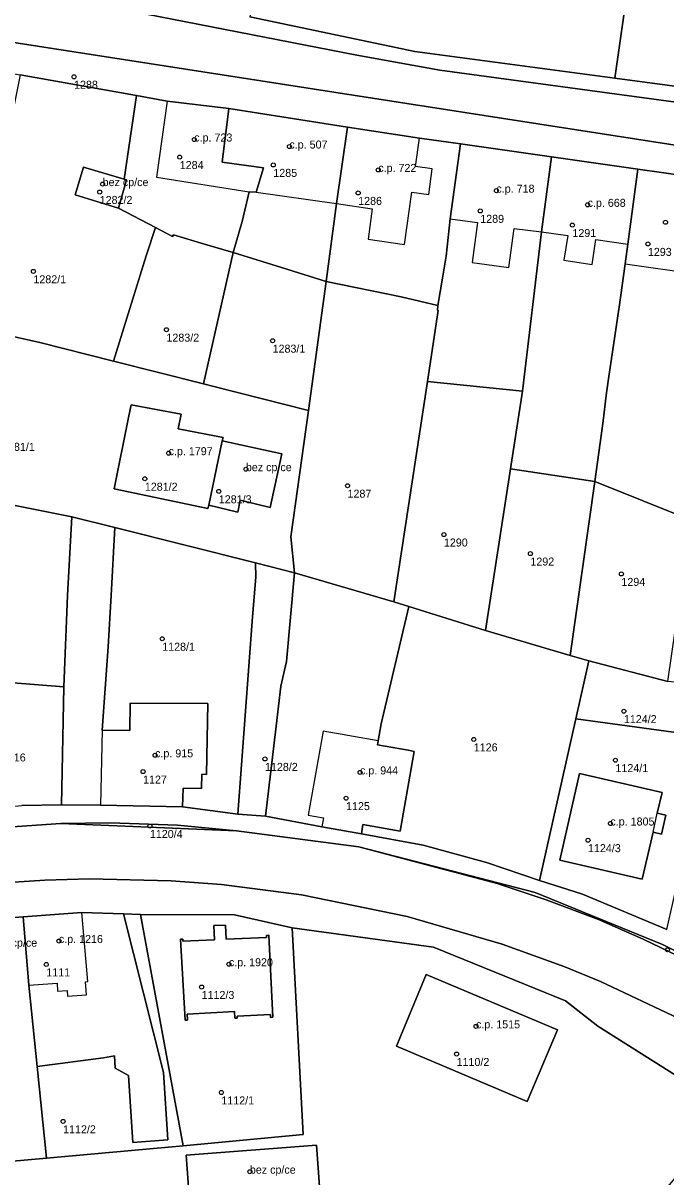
# Model space of a CAD drawing. Extents: x -878211 to -870363, y -1058464 to -1052522.
# Drawn here: x -875220.6 to -875140.3, y -1056399.9 to -1056255.7 of the extents above; entities that cross this region are included whole.
import ezdxf

# ---------------------------------------------------------------- set-up
doc = ezdxf.new("R2010")
doc.units = 0
for name, color, linetype in [('Definiční body', 7, 'Continuous'), ('Polygon budovy', 7, 'Continuous'), ('Polygon parcely', 7, 'Continuous')]:
    doc.layers.add(name, color=color, linetype=linetype)

msp = doc.modelspace()

# ---------------------------------------------------------------- linework, layer by layer
at = {"layer": 'Definiční body'}
for centre in [(-875214.21, -1056262.45994), (-875199.2, -1056270.28994), (-875187.31, -1056271.16994), (-875201.01, -1056272.48994), (-875189.32, -1056273.46994), (-875176.21, -1056274.08994), (-875211.01, -1056276.84994), (-875210.64, -1056275.85994), (-875178.72, -1056276.96994), (-875161.45, -1056276.67994), (-875150.06, -1056278.44994), (-875163.47, -1056279.20994), (-875151.96, -1056280.97994), (-875140.33, -1056280.62994), (-875142.53, -1056283.33994), (-875219.29, -1056286.75994), (-875202.67, -1056294.04994), (-875189.41, -1056295.42994), (-875202.4, -1056309.46994), (-875192.75, -1056311.46994), (-875205.37, -1056312.66994), (-875196.13, -1056314.23994), (-875180.05, -1056313.53994), (-875168.01, -1056319.63994), (-875157.21, -1056322.01994), (-875145.84, -1056324.55994), (-875203.2, -1056332.65994), (-875145.53, -1056341.69994), (-875164.28, -1056345.22994), (-875204.09, -1056347.20994), (-875190.36, -1056347.66994), (-875146.58, -1056347.81994), (-875205.59, -1056349.24994), (-875178.49, -1056349.34994), (-875180.23, -1056352.56994), (-875204.74, -1056356.04994), (-875147.21, -1056355.72994), (-875150.01, -1056357.81994), (-875216.11, -1056370.40994), (-875140.09, -1056371.49994), (-875217.68, -1056373.33994), (-875194.87, -1056373.30994), (-875198.28, -1056376.15994), (-875164, -1056381.06994), (-875166.43, -1056384.52994), (-875195.81, -1056389.32994), (-875215.58, -1056392.93994), (-875192.25, -1056399.21994)]:
    msp.add_circle(centre, 0.25, dxfattribs=at)
at = {"layer": 'Polygon budovy'}
for points in [[(-875202.57, -1056265.49), (-875203.92, -1056274.99), (-875192.33, -1056276.81), (-875191.47, -1056276.86), (-875190.56, -1056273.84), (-875195.72, -1056273.13), (-875194.86, -1056266.4)], [(-875195.72, -1056273.13), (-875190.56, -1056273.84), (-875191.47, -1056276.86), (-875181.41, -1056278.29), (-875180.06, -1056268.76), (-875194.86, -1056266.4)], [(-875181.41, -1056278.29), (-875176.96, -1056278.96), (-875177.48, -1056282.72), (-875172.95, -1056283.4), (-875172.02, -1056276.88), (-875169.91, -1056277.17), (-875169.48, -1056273.97), (-875171.56, -1056273.68), (-875171.07, -1056270.14), (-875180.06, -1056268.76)], [(-875165.93, -1056270.84), (-875167.22, -1056280.18), (-875163.8, -1056280.65), (-875164.49, -1056285.66), (-875159.9, -1056286.29), (-875159.23, -1056281.4), (-875155.83, -1056281.83), (-875154.56, -1056272.47)], [(-875155.83, -1056281.83), (-875152.55, -1056282.29), (-875153.05, -1056285.38), (-875149.49, -1056285.91), (-875149.02, -1056282.76), (-875145.04, -1056283.35), (-875143.8, -1056273.98), (-875154.56, -1056272.47)], [(-875214.07, -1056277.19), (-875208.66, -1056278.87), (-875207.68, -1056275.34), (-875207.97, -1056275.25), (-875213.03, -1056273.73)], [(-875145.04, -1056283.35), (-875145.36, -1056285.83), (-875136.58, -1056287.05), (-875134.93, -1056275.24), (-875143.8, -1056273.98)], [(-875200.84, -1056304.61), (-875207.07, -1056303.42), (-875207.4, -1056305.03), (-875209.2, -1056313.93), (-875197.48, -1056316.38), (-875197.39, -1056315.98), (-875195.69, -1056307.93), (-875195.6, -1056307.52), (-875201.2, -1056306.43)], [(-875193.75, -1056316.82), (-875193.45, -1056315.36), (-875189.72, -1056316.27), (-875188.26, -1056309.57), (-875195.69, -1056307.93), (-875197.39, -1056315.98)], [(-875207.2, -1056340.68), (-875207.25, -1056344.13), (-875210.71, -1056344.08), (-875210.92, -1056353.44), (-875200.68, -1056353.65), (-875200.6, -1056351.3), (-875198.28, -1056351.37), (-875198.23, -1056349.55), (-875197.68, -1056349.59), (-875197.51, -1056340.74)], [(-875184.97, -1056354.7), (-875183.06, -1056355.04), (-875183.26, -1056356.13), (-875178.32, -1056357), (-875178.13, -1056355.87), (-875173.49, -1056356.67), (-875171.71, -1056346.72), (-875172.46, -1056346.58), (-875176.3, -1056345.89), (-875176.21, -1056345.39), (-875183.08, -1056344.18)], [(-875151.09, -1056349.5), (-875153.52, -1056360.3), (-875143.24, -1056362.68), (-875141.89, -1056356.81), (-875141.35, -1056354.44), (-875140.76, -1056351.84)], [(-875212.79, -1056375.5), (-875212.51, -1056375.48), (-875213.23, -1056366.84), (-875220.56, -1056367.39), (-875219.86, -1056375.93), (-875216.34, -1056375.68), (-875216.27, -1056376.69), (-875215.09, -1056376.6), (-875215.04, -1056377.31), (-875212.66, -1056377.14)], [(-875200.08, -1056379.54), (-875194.18, -1056379.2), (-875194.13, -1056380.05), (-875193.83, -1056380.03), (-875193.84, -1056379.81), (-875189.69, -1056379.57), (-875189.67, -1056379.95), (-875189.37, -1056379.93), (-875189.86, -1056369.68), (-875190.16, -1056369.7), (-875190.16, -1056369.95), (-875195.22, -1056370.16), (-875195.29, -1056368.42), (-875196.77, -1056368.46), (-875196.68, -1056370.26), (-875200.63, -1056370.44), (-875200.64, -1056370.17), (-875200.93, -1056370.19), (-875200.34, -1056380.31), (-875200.04, -1056380.29)], [(-875173.95, -1056383.55), (-875157.61, -1056390.46), (-875153.81, -1056381.51), (-875170.22, -1056374.59)], [(-875183.93, -1056395.9), (-875200.2, -1056397.17), (-875199.65, -1056404.55), (-875183.4, -1056403.37)]]:
    msp.add_lwpolyline(points, close=True, dxfattribs=at)
at = {"layer": 'Polygon parcely'}
for points in [[(-875192.25, -1056254.98), (-875171.65, -1056259.31), (-875146.64, -1056262.62), (-875145.45, -1056254.19), (-875143.49, -1056240.36), (-875142.76, -1056235.27), (-875163.85, -1056231.52), (-875186.44, -1056227.59)], [(-875146.64, -1056262.62), (-875100.28, -1056268.85), (-875099.3, -1056262.14), (-875092.6, -1056263.05), (-875091.28, -1056254.4), (-875090.54, -1056254.77), (-875089.5, -1056246.85), (-875096.96, -1056245.76), (-875099.09, -1056260.33), (-875130.54, -1056255.84), (-875128.5, -1056241.21), (-875121.77, -1056242.17), (-875121.8, -1056242.36), (-875116.62, -1056243.08), (-875116.46, -1056241.92), (-875140.94, -1056235.59), (-875142.76, -1056235.27), (-875143.49, -1056240.36), (-875145.45, -1056254.19)], [(-875209.27, -1056297.99), (-875205.22, -1056284.84), (-875204.02, -1056281.27), (-875208.66, -1056278.87), (-875214.07, -1056277.19), (-875213.03, -1056273.73), (-875207.97, -1056275.25), (-875206.4, -1056264.8), (-875220.93, -1056262.2), (-875223.93, -1056277.04), (-875226.69, -1056276.6), (-875229.33, -1056293.22), (-875218.47, -1056295.66)], [(-875201.8, -1056282.21), (-875197.91, -1056283.35), (-875194.35, -1056284.4), (-875193.23, -1056280.52), (-875192.33, -1056276.81), (-875191.47, -1056276.86), (-875190.56, -1056273.84), (-875195.72, -1056273.13), (-875194.86, -1056266.4), (-875202.57, -1056265.49), (-875206.4, -1056264.8), (-875207.97, -1056275.25), (-875207.68, -1056275.34), (-875208.66, -1056278.87), (-875204.02, -1056281.27), (-875201.92, -1056282.42)], [(-875188.3, -1056286.27), (-875182.73, -1056288.01), (-875181.41, -1056278.29), (-875180.06, -1056268.76), (-875194.86, -1056266.4), (-875195.72, -1056273.13), (-875190.56, -1056273.84), (-875191.47, -1056276.86), (-875192.33, -1056276.81), (-875193.23, -1056280.52), (-875194.35, -1056284.4)], [(-875182.73, -1056288.01), (-875173.36, -1056289.95), (-875168.76, -1056291.01), (-875168.18, -1056287.6), (-875167.71, -1056284.87), (-875167.22, -1056280.18), (-875165.93, -1056270.84), (-875171.07, -1056270.14), (-875180.06, -1056268.76), (-875181.41, -1056278.29)], [(-875167.22, -1056280.18), (-875167.71, -1056284.87), (-875168.18, -1056287.6), (-875168.76, -1056291.01), (-875168.83, -1056291.61), (-875168.72, -1056291.64), (-875170.07, -1056300.5), (-875158.18, -1056301.72), (-875155.83, -1056281.83), (-875154.56, -1056272.47), (-875165.93, -1056270.84)], [(-875149.17, -1056313.02), (-875148.15, -1056305.75), (-875147.69, -1056301.93), (-875147.43, -1056300.19), (-875146.14, -1056291.49), (-875146.1, -1056291.25), (-875145.36, -1056285.83), (-875145.04, -1056283.35), (-875143.8, -1056273.98), (-875154.56, -1056272.47), (-875155.83, -1056281.83), (-875158.18, -1056301.72), (-875159.68, -1056311.41)], [(-875208.66, -1056278.87), (-875207.68, -1056275.34), (-875207.97, -1056275.25), (-875213.03, -1056273.73), (-875214.07, -1056277.19)], [(-875137.13, -1056317.85), (-875134.54, -1056299.86), (-875134.06, -1056296.75), (-875133.71, -1056293.63), (-875133.17, -1056289.86), (-875131.07, -1056275.73), (-875134.93, -1056275.24), (-875143.8, -1056273.98), (-875145.04, -1056283.35), (-875145.36, -1056285.83), (-875146.1, -1056291.25), (-875146.14, -1056291.49), (-875147.43, -1056300.19), (-875147.69, -1056301.93), (-875148.15, -1056305.75), (-875149.17, -1056313.02)], [(-875194.35, -1056284.4), (-875197.91, -1056283.35), (-875201.8, -1056282.21), (-875201.92, -1056282.42), (-875204.02, -1056281.27), (-875205.22, -1056284.84), (-875209.27, -1056297.99), (-875198.04, -1056300.81)], [(-875198.04, -1056300.81), (-875196.77, -1056301.13), (-875184.93, -1056304.16), (-875182.73, -1056288.01), (-875188.3, -1056286.27), (-875194.35, -1056284.4)], [(-875182.73, -1056288.01), (-875184.93, -1056304.16), (-875187.15, -1056319.92), (-875186.69, -1056324.41), (-875174.26, -1056328.03), (-875170.07, -1056300.5), (-875168.72, -1056291.64), (-875168.83, -1056291.61), (-875168.76, -1056291.01), (-875173.36, -1056289.95)], [(-875184.93, -1056304.16), (-875196.77, -1056301.13), (-875198.04, -1056300.81), (-875209.27, -1056297.99), (-875218.47, -1056295.66), (-875229.33, -1056293.22), (-875229.96, -1056296.23), (-875232.61, -1056313.8), (-875214.5, -1056317.42), (-875209.11, -1056318.77), (-875191.55, -1056323.16), (-875186.69, -1056324.41), (-875187.15, -1056319.92)], [(-875158.18, -1056301.72), (-875170.07, -1056300.5), (-875174.26, -1056328.03), (-875172.4, -1056328.62), (-875162.8, -1056331.64), (-875159.68, -1056311.41)], [(-875195.69, -1056307.93), (-875195.6, -1056307.52), (-875201.2, -1056306.43), (-875200.84, -1056304.61), (-875207.07, -1056303.42), (-875207.4, -1056305.03), (-875209.2, -1056313.93), (-875197.48, -1056316.38), (-875197.39, -1056315.98)], [(-875195.69, -1056307.93), (-875188.26, -1056309.57), (-875189.72, -1056316.27), (-875193.45, -1056315.36), (-875193.75, -1056316.82), (-875197.39, -1056315.98), (-875197.48, -1056316.38), (-875209.2, -1056313.93), (-875207.4, -1056305.03), (-875207.07, -1056303.42), (-875200.84, -1056304.61), (-875201.2, -1056306.43), (-875195.6, -1056307.52)], [(-875197.39, -1056315.98), (-875193.75, -1056316.82), (-875193.45, -1056315.36), (-875189.72, -1056316.27), (-875188.26, -1056309.57), (-875195.69, -1056307.93)], [(-875149.17, -1056313.02), (-875159.68, -1056311.41), (-875162.8, -1056331.64), (-875152.23, -1056334.75)], [(-875215.01, -1056327.24), (-875214.5, -1056317.42), (-875232.61, -1056313.8), (-875231.57, -1056331.78), (-875226.06, -1056332.37), (-875226.49, -1056336.38), (-875226.66, -1056337.79), (-875215.5, -1056338.65)], [(-875137.13, -1056317.85), (-875149.17, -1056313.02), (-875152.23, -1056334.75), (-875149.92, -1056335.39), (-875140.03, -1056338)], [(-875215.5, -1056338.65), (-875215.78, -1056353.41), (-875210.92, -1056353.44), (-875200.68, -1056353.65), (-875200.6, -1056351.3), (-875198.28, -1056351.37), (-875198.23, -1056349.55), (-875197.68, -1056349.59), (-875197.51, -1056340.74), (-875207.2, -1056340.68), (-875207.25, -1056344.13), (-875210.71, -1056344.08), (-875209.97, -1056333.68), (-875209.59, -1056327.26), (-875209.11, -1056318.77), (-875214.5, -1056317.42), (-875215.01, -1056327.24)], [(-875191.55, -1056323.16), (-875209.11, -1056318.77), (-875209.59, -1056327.26), (-875209.97, -1056333.68), (-875210.71, -1056344.08), (-875207.25, -1056344.13), (-875207.2, -1056340.68), (-875197.51, -1056340.74), (-875197.68, -1056349.59), (-875198.23, -1056349.55), (-875198.28, -1056351.37), (-875200.6, -1056351.3), (-875200.68, -1056353.65), (-875193.76, -1056354.57), (-875191.9, -1056329.92), (-875191.52, -1056324.94)], [(-875191.55, -1056323.16), (-875191.52, -1056324.94), (-875191.9, -1056329.92), (-875193.76, -1056354.57), (-875190.28, -1056354.81), (-875188.95, -1056343.56), (-875188.37, -1056338.56), (-875187.68, -1056335.49), (-875186.69, -1056324.41)], [(-875183.26, -1056356.13), (-875178.32, -1056357), (-875178.13, -1056355.87), (-875173.49, -1056356.67), (-875171.71, -1056346.72), (-875172.46, -1056346.58), (-875176.3, -1056345.89), (-875176.21, -1056345.39), (-875175.84, -1056343.29), (-875172.4, -1056328.62), (-875174.26, -1056328.03), (-875186.69, -1056324.41), (-875187.68, -1056335.49), (-875188.37, -1056338.56), (-875188.95, -1056343.56), (-875190.28, -1056354.81)], [(-875170.6, -1056358.44), (-875162.71, -1056360.61), (-875156.07, -1056362.83), (-875151.54, -1056342.64), (-875149.92, -1056335.39), (-875152.23, -1056334.75), (-875162.8, -1056331.64), (-875172.4, -1056328.62), (-875175.84, -1056343.29), (-875176.21, -1056345.39), (-875176.3, -1056345.89), (-875172.46, -1056346.58), (-875171.71, -1056346.72), (-875173.49, -1056356.67), (-875178.13, -1056355.87), (-875178.32, -1056357)], [(-875220.75, -1056353.48), (-875215.78, -1056353.41), (-875215.5, -1056338.65), (-875226.66, -1056337.79), (-875226.49, -1056336.38), (-875226.06, -1056332.37), (-875231.57, -1056331.78), (-875231.16, -1056335.82), (-875230.75, -1056340.36), (-875230.31, -1056345.3), (-875229.41, -1056354.3)], [(-875151.54, -1056342.64), (-875134.75, -1056344.94), (-875133.33, -1056338.6), (-875140.03, -1056338), (-875149.92, -1056335.39)], [(-875150.71, -1056364.56), (-875140.15, -1056368.99), (-875137, -1056354.96), (-875134.75, -1056344.94), (-875151.54, -1056342.64), (-875156.07, -1056362.83)], [(-875153.52, -1056360.3), (-875143.24, -1056362.68), (-875141.89, -1056356.81), (-875140.81, -1056357.05), (-875140.28, -1056354.68), (-875141.35, -1056354.44), (-875140.76, -1056351.84), (-875151.09, -1056349.5)], [(-875153.52, -1056360.3), (-875151.09, -1056349.5), (-875140.76, -1056351.84), (-875141.35, -1056354.44), (-875140.28, -1056354.68), (-875140.81, -1056357.05), (-875141.89, -1056356.81), (-875143.24, -1056362.68)], [(-875215.85, -1056355.72), (-875193.92, -1056356.66), (-875201.3, -1056355.92), (-875209.72, -1056355.65)], [(-875140.69, -1056370.83), (-875156.63, -1056364.33), (-875178.63, -1056358.65), (-875161.34, -1056363.22), (-875155.23, -1056365.27), (-875148.68, -1056367.74), (-875143.11, -1056370.16), (-875126.03, -1056378.37), (-875124.79, -1056378.79)], [(-875218.82, -1056386.07), (-875219.86, -1056375.93), (-875220.56, -1056367.39), (-875223.22, -1056367.59), (-875222.58, -1056373.85), (-875226.22, -1056374.28), (-875226.86, -1056367.97), (-875230.49, -1056368.33), (-875230.06, -1056372.07), (-875228.79, -1056383.11), (-875227.04, -1056398.38), (-875217.64, -1056397.55)], [(-875218.82, -1056386.07), (-875210.54, -1056385), (-875209.14, -1056384.75), (-875209.07, -1056386.31), (-875207.43, -1056387.19), (-875206.85, -1056395.59), (-875202.5, -1056395.26), (-875203.04, -1056386.84), (-875208.05, -1056367.03), (-875213.23, -1056366.84), (-875220.56, -1056367.39), (-875219.86, -1056375.93)], [(-875217.64, -1056397.55), (-875200.57, -1056396.01), (-875205.91, -1056367.11), (-875208.05, -1056367.03), (-875203.04, -1056386.84), (-875202.5, -1056395.26), (-875206.85, -1056395.59), (-875207.43, -1056387.19), (-875209.07, -1056386.31), (-875209.14, -1056384.75), (-875210.54, -1056385), (-875218.82, -1056386.07)], [(-875200.57, -1056396.01), (-875185.58, -1056394.58), (-875186.95, -1056368.75), (-875194.18, -1056367.12), (-875205.91, -1056367.11)], [(-875200.57, -1056396.01), (-875217.64, -1056397.55), (-875227.04, -1056398.38), (-875237.58, -1056399.31), (-875235.99, -1056416.34), (-875254.11, -1056418.23), (-875254.73, -1056418.15), (-875247.86, -1056467.52), (-875278.14, -1056485.01), (-875275.46, -1056496.62), (-875270.88, -1056517.13), (-875266.18, -1056516.99), (-875187.17, -1056501.5), (-875197.07, -1056487.59), (-875170.85, -1056444.56), (-875168.16, -1056440.42), (-875162.37, -1056427.89), (-875132.07, -1056391.57), (-875148.79, -1056381.04), (-875152.82, -1056377.86), (-875169.32, -1056371.19), (-875186.95, -1056368.75), (-875185.58, -1056394.58)], [(-875196.68, -1056370.26), (-875200.63, -1056370.44), (-875200.64, -1056370.17), (-875200.93, -1056370.19), (-875200.34, -1056380.31), (-875200.04, -1056380.29), (-875200.08, -1056379.54), (-875194.18, -1056379.2), (-875194.13, -1056380.05), (-875193.83, -1056380.03), (-875193.84, -1056379.81), (-875189.69, -1056379.57), (-875189.67, -1056379.95), (-875189.37, -1056379.93), (-875189.86, -1056369.68), (-875190.16, -1056369.7), (-875190.16, -1056369.95), (-875195.22, -1056370.16), (-875195.29, -1056368.42), (-875196.77, -1056368.46)], [(-875196.68, -1056370.26), (-875196.77, -1056368.46), (-875195.29, -1056368.42), (-875195.22, -1056370.16), (-875190.16, -1056369.95), (-875190.16, -1056369.7), (-875189.86, -1056369.68), (-875189.37, -1056379.93), (-875189.67, -1056379.95), (-875189.69, -1056379.57), (-875193.84, -1056379.81), (-875193.83, -1056380.03), (-875194.13, -1056380.05), (-875194.18, -1056379.2), (-875200.08, -1056379.54), (-875200.04, -1056380.29), (-875200.34, -1056380.31), (-875200.93, -1056370.19), (-875200.64, -1056370.17), (-875200.63, -1056370.44)], [(-875157.61, -1056390.46), (-875153.81, -1056381.51), (-875170.22, -1056374.59), (-875173.95, -1056383.55)], [(-875157.61, -1056390.46), (-875173.95, -1056383.55), (-875170.22, -1056374.59), (-875153.81, -1056381.51)], [(-875183.93, -1056395.9), (-875200.2, -1056397.17), (-875199.65, -1056404.55), (-875183.4, -1056403.37)], [(-875183.93, -1056395.9), (-875183.4, -1056403.37), (-875199.65, -1056404.55), (-875200.2, -1056397.17)]]:
    msp.add_lwpolyline(points, close=True, dxfattribs=at)
for points in [[(-875134.42, -1056266.24), (-875168.5, -1056261.62), (-875178.88, -1056259.75), (-875211.79, -1056253.35), (-875239.65, -1056248.32), (-875262.18, -1056244.25), (-875281.49, -1056241.14), (-875288.38, -1056240.11), (-875292.78, -1056239.47), (-875294.43, -1056238.67)], [(-875076.87, -1056280.65), (-875298.24, -1056246.26), (-875300.2, -1056248.02), (-875292.88, -1056249.17), (-875281.01, -1056251.4), (-875271.78, -1056253.11), (-875268.54, -1056253.62), (-875262.65, -1056254.71), (-875256.18, -1056255.88), (-875249.73, -1056257.07), (-875244.49, -1056257.99), (-875242.9, -1056258.33), (-875234.19, -1056259.84), (-875225.15, -1056261.48), (-875220.93, -1056262.2), (-875206.4, -1056264.8), (-875202.57, -1056265.49), (-875194.86, -1056266.4), (-875180.06, -1056268.76), (-875171.07, -1056270.14), (-875165.93, -1056270.84), (-875154.56, -1056272.47), (-875143.8, -1056273.98), (-875134.93, -1056275.24)], [(-875300.2, -1056248.02), (-875298.24, -1056246.26), (-875076.87, -1056280.65)], [(-875211.79, -1056253.35), (-875178.88, -1056259.75), (-875168.5, -1056261.62), (-875134.42, -1056266.24)], [(-875100.28, -1056268.85), (-875146.64, -1056262.62), (-875171.65, -1056259.31), (-875192.25, -1056254.98)], [(-875140.15, -1056368.99), (-875150.71, -1056364.56), (-875156.07, -1056362.83), (-875162.71, -1056360.61), (-875170.6, -1056358.44), (-875178.32, -1056357), (-875183.26, -1056356.13), (-875190.28, -1056354.81), (-875193.76, -1056354.57), (-875200.68, -1056353.65), (-875210.92, -1056353.44), (-875215.78, -1056353.41), (-875220.75, -1056353.48)], [(-875409.01, -1056395.8), (-875400.76, -1056392.35), (-875383.29, -1056385.23), (-875375.34, -1056382.19), (-875367.42, -1056379.44), (-875352.88, -1056375.12), (-875344.63, -1056373.02), (-875337.67, -1056371.42), (-875325.65, -1056368.89), (-875301.06, -1056364.21), (-875283.21, -1056361.69), (-875277.03, -1056360.91), (-875267.21, -1056359.9), (-875241.87, -1056357.54), (-875215.85, -1056355.72), (-875209.72, -1056355.65), (-875201.3, -1056355.92), (-875193.92, -1056356.66), (-875178.63, -1056358.65), (-875156.63, -1056364.33), (-875140.69, -1056370.83), (-875124.79, -1056378.79)], [(-875178.63, -1056358.65), (-875193.92, -1056356.66), (-875215.85, -1056355.72), (-875241.87, -1056357.54), (-875301.06, -1056364.21), (-875325.65, -1056368.89), (-875333.52, -1056370.91), (-875336.44, -1056371.66), (-875357.27, -1056377.02), (-875390.07, -1056388.31), (-875408.68, -1056396.75)], [(-875126.03, -1056378.37), (-875143.11, -1056370.16), (-875148.68, -1056367.74), (-875155.23, -1056365.27), (-875161.34, -1056363.22), (-875178.63, -1056358.65)], [(-875306.02, -1056372.36), (-875292.24, -1056370.08), (-875280.78, -1056368.45), (-875259.86, -1056366.33), (-875232.06, -1056363.91), (-875224.33, -1056363.24), (-875217.87, -1056362.82), (-875212.3, -1056362.66), (-875202.09, -1056362.9), (-875195.78, -1056363.36), (-875185.82, -1056364.63), (-875172.58, -1056367.36), (-875160.72, -1056370.8), (-875152.9, -1056373.65), (-875148.44, -1056375.46), (-875129.04, -1056384.62)], [(-875129.04, -1056384.62), (-875148.44, -1056375.46), (-875152.9, -1056373.65), (-875160.72, -1056370.8), (-875172.58, -1056367.36), (-875185.82, -1056364.63), (-875195.78, -1056363.36), (-875202.09, -1056362.9), (-875212.3, -1056362.66), (-875217.87, -1056362.82), (-875224.33, -1056363.24), (-875232.06, -1056363.91), (-875259.86, -1056366.33), (-875280.78, -1056368.45), (-875292.24, -1056370.08), (-875306.02, -1056372.36)], [(-875326.1, -1056378.2), (-875297.94, -1056375.24), (-875274.52, -1056372.72), (-875272.16, -1056373.18), (-875259.77, -1056372.06), (-875254.93, -1056371.72), (-875249.82, -1056371.56), (-875249.94, -1056370.25), (-875240.65, -1056369.3), (-875232.98, -1056368.57), (-875230.49, -1056368.33), (-875226.86, -1056367.97), (-875223.22, -1056367.59), (-875220.56, -1056367.39), (-875213.23, -1056366.84), (-875208.05, -1056367.03), (-875205.91, -1056367.11), (-875194.18, -1056367.12), (-875186.95, -1056368.75), (-875169.32, -1056371.19), (-875152.82, -1056377.86), (-875148.79, -1056381.04), (-875132.07, -1056391.57)]]:
    msp.add_lwpolyline(points, dxfattribs=at)

# ---------------------------------------------------------------- texts
at = {"layer": 'Definiční body'}
for s, p in [('1288', (-875214.21, -1056263.949)), ('c.p. 723', (-875199.2, -1056270.54)), ('c.p. 507', (-875187.31, -1056271.419)), ('1284', (-875201.01, -1056273.979)), ('1285', (-875189.32, -1056274.959)), ('c.p. 722', (-875176.21, -1056274.34)), ('bez cp/ce', (-875210.64, -1056276.11)), ('c.p. 718', (-875161.45, -1056276.929)), ('1282/2', (-875211.01, -1056278.339)), ('1286', (-875178.72, -1056278.459)), ('c.p. 668', (-875150.06, -1056278.7)), ('1289', (-875163.47, -1056280.699)), ('1291', (-875151.96, -1056282.469)), ('1293', (-875142.53, -1056284.829)), ('1282/1', (-875219.29, -1056288.249)), ('1283/2', (-875202.67, -1056295.539)), ('1283/1', (-875189.41, -1056296.919)), ('1281/1', (-875223.21, -1056309.179)), ('c.p. 1797', (-875202.4, -1056309.72)), ('bez cp/ce', (-875192.75, -1056311.72)), ('1281/2', (-875205.37, -1056314.159)), ('1287', (-875180.05, -1056315.029)), ('1281/3', (-875196.13, -1056315.729)), ('1290', (-875168.01, -1056321.129)), ('1292', (-875157.21, -1056323.509)), ('1294', (-875145.84, -1056326.049)), ('1128/1', (-875203.2, -1056334.149)), ('1124/2', (-875145.53, -1056343.189)), ('1126', (-875164.28, -1056346.719)), ('c.p. 916', (-875225.01, -1056347.98)), ('c.p. 915', (-875204.09, -1056347.46)), ('1128/2', (-875190.36, -1056349.159)), ('c.p. 944', (-875178.49, -1056349.6)), ('1124/1', (-875146.58, -1056349.309)), ('1127', (-875205.59, -1056350.739)), ('1125', (-875180.23, -1056354.059)), ('c.p. 1805', (-875147.21, -1056355.98)), ('1120/4', (-875204.74, -1056357.539)), ('1124/3', (-875150.01, -1056359.309)), ('bez cp/ce', (-875224.54, -1056371.12)), ('c.p. 1216', (-875216.11, -1056370.659)), ('c.p. 1920', (-875194.87, -1056373.56)), ('1111', (-875217.68, -1056374.829)), ('1112/3', (-875198.28, -1056377.649)), ('c.p. 1515', (-875164, -1056381.32)), ('1110/2', (-875166.43, -1056386.019)), ('1112/1', (-875195.81, -1056390.819)), ('1112/2', (-875215.58, -1056394.429)), ('bez cp/ce', (-875192.25, -1056399.47))]:
    msp.add_text(s, height=0.999996, dxfattribs=at).set_placement(p)

doc.saveas('drawing.dxf')
